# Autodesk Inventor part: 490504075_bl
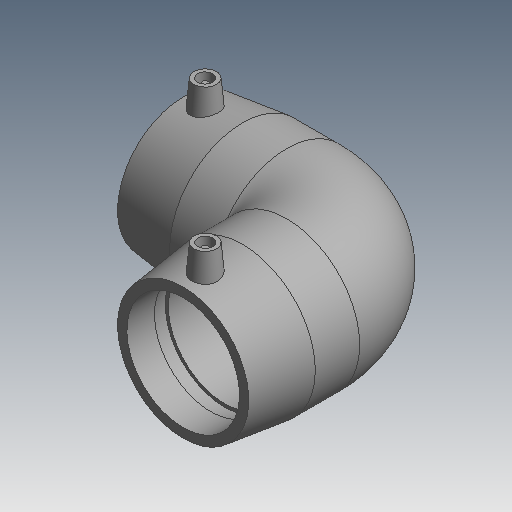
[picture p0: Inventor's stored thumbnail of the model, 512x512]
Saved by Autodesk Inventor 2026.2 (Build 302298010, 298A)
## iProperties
Created: 2017-06
Part Number: 490504075_bl
Material: Generic
Description: PLASSON 90° ELBOW 75
Document SubType Name: Modeling
Designer: KIM
Mass: 55.0731 g
Surface Area: 148.067 cm^2
Volume: 55.0731 cm^3
Density: 1 g/cm^3
Appearance: Default
Author: KIM
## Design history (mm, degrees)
derived "490504 -20-75.ipt"
feature "Solid1::490504 -20-75.ipt" dims "ScaleForDerivedMember" = 10
tag "TaggingFeature1"
body "Solid1"
other parameters: "d2" = 97 [user parameter], "d4" = 39.5 [user parameter], "d5" = 87.3 [user parameter], "d8" = 168 deg [user parameter], "d10" = 27.6 [user parameter], "d11" = 9.2 [user parameter], "d14" = 17.6296 [user parameter], "d18" = 75 [user parameter], "d19" = 3.52592 [user parameter], "d20" = 168 deg [user parameter], "d22" = 89.24 [user parameter], "d23" = 97 [user parameter], "d24" = 86.5628 [user parameter], "d29" = 62 [user parameter], "d30" = 15 [user parameter], "d31" = 94.8 [user parameter], "d34" = 5 deg [user parameter], "d35" = 15 [user parameter], "d39" = 5 deg [user parameter], "d41" = 4 [user parameter], "d42" = 14 [user parameter], "d43" = 0 [user parameter], "d45" = 4 [user parameter], "d46" = 14 [user parameter], "d47" = 0 [user parameter], "d49" = 75 [user parameter], "d50" = 63.75 [user parameter], "d51" = 27.6 [user parameter], "d52" = 69 [user parameter], "d54" = 90 deg [user parameter], "d65" = 75 [user parameter], "d67" = 45 deg [user parameter], "d71" = 90 deg [user parameter], "d75" = 4.85 [user parameter], "d82" = 45 deg [user parameter], "d83" = 69 [user parameter], "d84" = 87.3 [user parameter], "d87" = 90 deg [user parameter], "d90" = 69 [user parameter], "d91" = 0 [user parameter], "d92" = 69 [user parameter], "d93" = 0 [user parameter], "d94" = 90 deg [user parameter], "d101" = 3 [user parameter], "d102" = 0 [user parameter], "d103" = 3 [user parameter], "d104" = 0 [user parameter], "d105" = 20.01 [user parameter], "d106" = 5.0025 [user parameter], "d110" = 37.95 [user parameter], "d111" = 158 [user parameter], "d112" = 158 [user parameter], "d113" = 158 [user parameter], "d114" = 158 [user parameter], "d_" = 75 [user parameter], "L_" = 158 [user parameter], "L_1" = 69 [user parameter], "D_" = 97 [user parameter], "A_" = 62 [user parameter], "d_2" = 12 [user parameter]
